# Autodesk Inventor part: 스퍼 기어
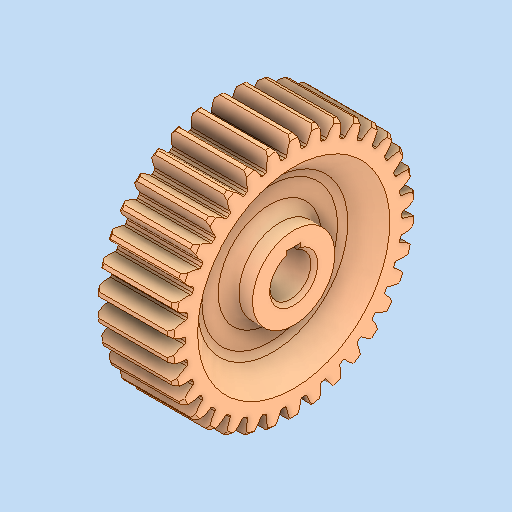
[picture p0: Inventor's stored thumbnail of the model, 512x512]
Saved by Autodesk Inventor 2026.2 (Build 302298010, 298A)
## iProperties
Created: 2026-03
Part Number: 스퍼 기어
Material: 강철, 합금
Document SubType Name: Modeling
Designer: PC-2-06
Density: 7.73 g/cm^3
Appearance: 기본값
Author: jhkim
Sending System: Autodesk Inventor 2026
Preprocessor: ST-DEVELOPER v20.1
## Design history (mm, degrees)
feature "솔리드1"
node "솔리드2"
